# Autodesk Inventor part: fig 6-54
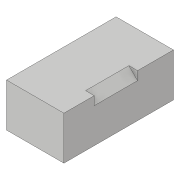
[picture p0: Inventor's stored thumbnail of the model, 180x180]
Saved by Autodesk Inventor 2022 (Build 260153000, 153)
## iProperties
Created: 2018-03
Part Number: fig 6-54
Material: Generic
Document SubType Name: Modeling
Designer: CADCIM 00
Density: 1 g/cm^3
Appearance: Default
Author: CADCIM 00
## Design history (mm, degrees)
sketch "Sketch1"
  geometry: L1 (0, 0)-(13.237, 0); L2 (13.237, 0)-(13.237, -25.282); L3 (13.237, -25.282)-(0, -25.282); L4 (0, -25.282)-(0, 0)
  constraints: 8 end point, 2 parallel, 1 horizontal, 1 perpendicular
extrude "Extrusion1" new body sketch "Sketch1" distance "d0" = 10; taper "d1" = 0 deg
chamfer "Chamfer1" distance "d2" = 2; stored, may be unused: second distance "d3" = 2, angle "d4" = 45 deg; dims "d5" = 7, "d6" = 10, "d7" = 8.28246
body "Solid1"
